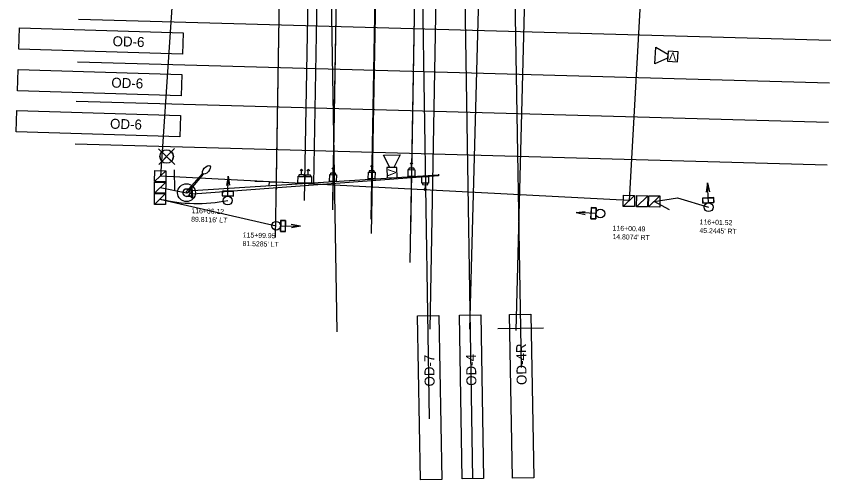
# Model space of a CAD drawing. Extents: x 925524 to 926006, y 853415 to 857998.
# Drawn here: x 925687.1 to 925916, y 853415.1 to 853545.3 of the extents above; entities that cross this region are included whole.
import ezdxf

# ---------------------------------------------------------------- set-up
doc = ezdxf.new("R2010")
doc.units = 0
for name, color, linetype in [('ConduitDB', 7, 'Continuous'), ('ConduitOT', 7, 'Continuous'), ('ConstLines', 7, 'Continuous'), ('Core', 7, 'Continuous'), ('DetectorVeh', 7, 'Continuous'), ('Luminaire', 7, 'Continuous'), ('NonPlottingEle_dp', 7, 'Continuous'), ('OverheadStr', 7, 'Continuous'), ('PedHead', 7, 'Continuous'), ('PoleFound', 7, 'Continuous'), ('PullBox', 7, 'Continuous'), ('ScratchEle2_dp', 7, 'Continuous'), ('ScratchEle_dp', 7, 'Continuous'), ('SignalHead', 7, 'Continuous'), ('SignPanel', 7, 'Continuous'), ('TextMinor', 7, 'Continuous')]:
    doc.layers.add(name, color=color, linetype=linetype)

msp = doc.modelspace()

# ---------------------------------------------------------------- linework, layer by layer
at = {"layer": 'ConduitDB'}
for p, q in [((925869.15, 853671.01), (925859.35, 853493.47)), ((925738.35, 853660.55), (925727.58, 853500.34)), ((925859.35, 853493.47), (925727.58, 853500.34)), ((925870.67, 853490.92), (925866.37, 853493.26))]:
    msp.add_line(p, q, dxfattribs=at)
msp.add_lwpolyline([(925866.37, 853493.26), (925872.9, 853494.28), (925881.63, 853491.63)], dxfattribs=at)
at = {"layer": 'ConduitOT'}
for p, q in [((925727.49, 853497.13), (925734.9, 853495.71)), ((925727.45, 853493.93), (925760.11, 853486.41))]:
    msp.add_line(p, q, dxfattribs=at)
msp.add_arc((925737.93, 853536.98), 44.31, 256.3165, 281.1337, dxfattribs=at)
at = {"layer": 'ConstLines'}
for p, q in [((925821.17, 853708.61), (925814.44, 853457.33)), ((925834.16, 853708.27), (925827.43, 853456.98)), ((925807.55, 853693.24), (925803.33, 853457.33)), ((925773.58, 853666.98), (925777.16, 853456.64))]:
    msp.add_line(p, q, dxfattribs=at)
at = {"layer": 'Core'}
for p, q in [((925727.08, 853508.03), (925731.66, 853503.6)), ((925727.15, 853503.62), (925731.54, 853508.16))]:
    msp.add_line(p, q, dxfattribs=at)
for points in [[(925727.95, 853507.19), (925729.32, 853505.86), (925728, 853504.5)], [(925730.64, 853507.23), (925729.32, 853505.86), (925730.69, 853504.54)]]:
    msp.add_lwpolyline(points, dxfattribs=at)
msp.add_circle((925729.32, 853505.86), 1.9, dxfattribs=at)
for start, end in [(135.9741, 225.9741), (315.9741, 45.9741)]:
    msp.add_arc((925729.32, 853505.86), 1.9, start, end, dxfattribs=at)
at = {"layer": 'DetectorVeh'}
for p, q in [((925870.19, 853534.66), (925870.12, 853533.49)), ((925793.21, 853502.77), (925792.04, 853502.75))]:
    msp.add_line(p, q, dxfattribs=at)
for points in [[(925870.12, 853533.49), (925866.5, 853531.95), (925866.78, 853536.63), (925870.19, 853534.66)], [(925792.04, 853502.75), (925790.23, 853506.24), (925794.91, 853506.32), (925793.21, 853502.77)]]:
    msp.add_lwpolyline(points, dxfattribs=at)
for points in [[(925870.07, 853532.67), (925872.87, 853532.5), (925873.04, 853535.31), (925870.24, 853535.48)], [(925791.22, 853502.74), (925791.27, 853499.93), (925794.08, 853499.98), (925794.03, 853502.79)]]:
    msp.add_lwpolyline(points, close=True, dxfattribs=at)
at = {"layer": 'Luminaire'}
for p, q in [((925739.42, 853501.09), (925734.75, 853495.85)), ((925739.61, 853500.93), (925735.06, 853495.58)), ((925735.06, 853495.58), (925734.75, 853495.85))]:
    msp.add_line(p, q, dxfattribs=at)
msp.add_ellipse((925740.48, 853502.12), major_axis=(0.98, 1.13), ratio=0.5, dxfattribs=at)
at = {"layer": 'NonPlottingEle_dp'}
for p, q in [((925763.22, 853675.01), (925759.78, 853483.16)), ((925779.22, 853674.95), (925775.92, 853490.92)), ((925790.22, 853674.76), (925786.81, 853484.28)), ((925801.22, 853674.56), (925797.82, 853484.67)), ((925704.58, 853544.44), (925915.95, 853538.55)), ((925704.24, 853532.45), (925915.62, 853526.55)), ((925703.94, 853521.45), (925915.31, 853515.56)), ((925703.6, 853509.46), (925914.98, 853503.56))]:
    msp.add_line(p, q, dxfattribs=at)
at = {"layer": 'OverheadStr'}
for p, q in [((925736.59, 853496.35), (925805.75, 853500.75)), ((925736.66, 853495.36), (925805.76, 853500.57)), ((925805.74, 853500.87), (925805.77, 853500.45)), ((925734.83, 853496.77), (925736.16, 853496.86)), ((925734.83, 853496.71), (925736.16, 853496.8)), ((925734.83, 853496.77), (925734.83, 853496.71)), ((925735.25, 853496.65), (925736.25, 853496.72)), ((925736.13, 853497.3), (925736.3, 853497.31)), ((925736.17, 853496.72), (925736.13, 853497.3)), ((925736.38, 853494.89), (925736.25, 853496.72)), ((925736.29, 853497.32), (925736.52, 853497.34)), ((925736.5, 853494.36), (925736.29, 853497.32)), ((925736.5, 853494.32), (925736.3, 853497.31)), ((925736.73, 853494.38), (925736.52, 853497.34)), ((925734.97, 853494.71), (925736.3, 853494.81)), ((925734.98, 853494.65), (925734.97, 853494.71)), ((925734.98, 853494.65), (925736.31, 853494.74)), ((925735.38, 853494.83), (925736.38, 853494.89)), ((925736.34, 853494.31), (925736.3, 853494.89)), ((925736.34, 853494.31), (925736.5, 853494.32)), ((925736.5, 853494.36), (925736.73, 853494.38))]:
    msp.add_line(p, q, dxfattribs=at)
msp.add_lwpolyline([(925735.92, 853495.51), (925735.88, 853496.05), (925735.58, 853496.49), (925735.1, 853496.73), (925734.57, 853496.69), (925734.12, 853496.39), (925733.89, 853495.91), (925733.92, 853495.37), (925734.22, 853494.93), (925734.7, 853494.69), (925735.24, 853494.73), (925735.68, 853495.03)], close=True, dxfattribs=at)
at = {"layer": 'PedHead'}
for p, q in [((925746.61, 853500.33), (925746.11, 853497.74)), ((925746.51, 853494.76), (925746.61, 853500.33)), ((925746.61, 853500.33), (925747.01, 853497.79)), ((925881.32, 853498.44), (925880.98, 853495.82)), ((925881.32, 853498.44), (925881.88, 853495.93)), ((925881.57, 853492.88), (925881.32, 853498.44)), ((925744.98, 853496.16), (925744.95, 853494.79)), ((925744.95, 853494.79), (925748.08, 853494.73)), ((925748.1, 853496.11), (925744.98, 853496.16)), ((925744.99, 853494.79), (925745.01, 853496.13)), ((925748.04, 853494.73), (925744.99, 853494.79)), ((925745.01, 853496.13), (925748.06, 853496.07)), ((925748.06, 853496.07), (925748.04, 853494.73)), ((925748.08, 853494.73), (925748.1, 853496.11)), ((925883.07, 853494.32), (925879.95, 853494.18)), ((925879.95, 853494.18), (925880.01, 853492.81)), ((925879.99, 853494.15), (925883.04, 853494.29)), ((925880.05, 853492.81), (925879.99, 853494.15)), ((925883.04, 853494.29), (925883.1, 853492.95)), ((925883.14, 853492.95), (925883.07, 853494.32)), ((925880.01, 853492.81), (925883.14, 853492.95)), ((925883.1, 853492.95), (925880.05, 853492.81)), ((925844.39, 853490.12), (925846.94, 853490.47)), ((925849.96, 853489.91), (925844.39, 853490.12)), ((925844.39, 853490.12), (925846.98, 853489.57)), ((925848.65, 853491.53), (925848.53, 853488.4)), ((925848.57, 853488.44), (925848.68, 853491.49)), ((925850.02, 853491.47), (925848.65, 853491.53)), ((925848.68, 853491.49), (925850.02, 853491.43)), ((925849.9, 853488.35), (925850.02, 853491.47)), ((925850.02, 853491.43), (925849.91, 853488.39)), ((925761.39, 853487.95), (925761.34, 853484.82)), ((925761.34, 853484.86), (925761.39, 853487.91)), ((925762.77, 853487.92), (925761.39, 853487.95)), ((925761.39, 853487.91), (925762.73, 853487.88)), ((925762.73, 853487.88), (925762.68, 853484.84)), ((925762.71, 853484.8), (925762.77, 853487.92)), ((925848.53, 853488.4), (925849.9, 853488.35)), ((925849.91, 853488.39), (925848.57, 853488.44)), ((925761.36, 853486.38), (925766.94, 853486.28)), ((925766.94, 853486.28), (925764.34, 853486.79)), ((925766.94, 853486.28), (925764.4, 853485.88)), ((925762.68, 853484.84), (925761.34, 853484.86)), ((925761.34, 853484.82), (925762.71, 853484.8))]:
    msp.add_line(p, q, dxfattribs=at)
for centre in [(925746.49, 853493.51), (925881.63, 853491.63), (925851.21, 853489.87), (925760.11, 853486.41)]:
    msp.add_circle(centre, 1.25, dxfattribs=at)
at = {"layer": 'PoleFound'}
msp.add_circle((925734.9, 853495.71), 2.5, dxfattribs=at)
at = {"layer": 'PullBox'}
for p, q in [((925725.94, 853498.81), (925725.98, 853501.94)), ((925725.94, 853498.81), (925729.1, 853501.89)), ((925725.98, 853501.94), (925729.1, 853501.89)), ((925729.1, 853501.89), (925729.06, 853498.77)), ((925725.91, 853495.59), (925725.95, 853498.71)), ((925725.91, 853495.59), (925729.08, 853498.67)), ((925729.06, 853498.77), (925725.94, 853498.81)), ((925725.95, 853498.71), (925729.08, 853498.67)), ((925729.08, 853498.67), (925729.03, 853495.55)), ((925725.87, 853492.39), (925725.91, 853495.52)), ((925725.87, 853492.39), (925729.04, 853495.47)), ((925729.03, 853495.55), (925725.91, 853495.59)), ((925725.91, 853495.52), (925729.04, 853495.47)), ((925729.04, 853495.47), (925728.99, 853492.35)), ((925857.67, 853491.85), (925857.73, 853494.97)), ((925857.67, 853491.85), (925860.85, 853494.92)), ((925857.73, 853494.97), (925860.85, 853494.92)), ((925860.85, 853494.92), (925860.8, 853491.79)), ((925861.39, 853491.78), (925861.44, 853494.91)), ((925861.39, 853491.78), (925864.57, 853494.85)), ((925861.44, 853494.91), (925864.57, 853494.85)), ((925864.57, 853494.85), (925864.51, 853491.73)), ((925864.78, 853491.72), (925864.83, 853494.85)), ((925864.78, 853491.72), (925867.96, 853494.79)), ((925864.83, 853494.85), (925867.96, 853494.79)), ((925867.96, 853494.79), (925867.9, 853491.67)), ((925728.99, 853492.35), (925725.87, 853492.39)), ((925860.8, 853491.79), (925857.67, 853491.85)), ((925864.51, 853491.73), (925861.39, 853491.78)), ((925867.9, 853491.67), (925864.78, 853491.72))]:
    msp.add_line(p, q, dxfattribs=at)
at = {"layer": 'ScratchEle2_dp'}
for p, q in [((925798.69, 853711.44), (925803.07, 853432.2)), ((925829.04, 853446.57), (925824.52, 853709.82)), ((925815.37, 853415.34), (925810.9, 853700.12)), ((925763.52, 853691.77), (925759.97, 853493.66)), ((925771.52, 853691.62), (925767.97, 853493.51)), ((925779.52, 853691.48), (925775.97, 853493.37)), ((925773.97, 853688.76), (925770.55, 853498.1)), ((925790.32, 853688.01), (925786.74, 853488.27)), ((925801.46, 853687.88), (925797.66, 853476.1)), ((925835.28, 853457.68), (925822.42, 853457.46))]:
    msp.add_line(p, q, dxfattribs=at)
at = {"layer": 'ScratchEle_dp'}
msp.add_line((925731.6, 853496.34), (925731.51, 853502.12), dxfattribs=at)
at = {"layer": 'SignalHead'}
for p, q in [((925786.58, 853503.09), (925786.99, 853503.48)), ((925786.96, 853501.87), (925786.99, 853503.48)), ((925787.38, 853503.07), (925786.99, 853503.48)), ((925797.76, 853503.8), (925798.17, 853504.19)), ((925798.14, 853502.58), (925798.17, 853504.19)), ((925798.56, 853503.78), (925798.17, 853504.19)), ((925766.82, 853501.9), (925767.23, 853502.3)), ((925767.2, 853500.69), (925767.23, 853502.3)), ((925767.62, 853501.89), (925767.23, 853502.3)), ((925768.73, 853501.87), (925769.13, 853502.26)), ((925769.1, 853500.65), (925769.13, 853502.26)), ((925769.52, 853501.86), (925769.13, 853502.26)), ((925776.72, 853501.17), (925775.49, 853501.19)), ((925775.73, 853502.39), (925776.14, 853502.79)), ((925776.11, 853501.18), (925776.14, 853502.79)), ((925776.53, 853502.38), (925776.14, 853502.79)), ((925787.57, 853501.86), (925786.35, 853501.88)), ((925798.75, 853502.57), (925797.52, 853502.59)), ((925767.81, 853500.68), (925766.58, 853500.7)), ((925769.72, 853500.64), (925768.49, 853500.66)), ((925801.35, 853497.98), (925802.58, 853497.96)), ((925801.54, 853496.77), (925801.93, 853496.36)), ((925801.96, 853497.97), (925801.93, 853496.36)), ((925802.34, 853496.75), (925801.93, 853496.36))]:
    msp.add_line(p, q, dxfattribs=at)
for points in [[(925786.02, 853501.49), (925787.89, 853501.46), (925787.86, 853499.58), (925785.98, 853499.62)], [(925797.19, 853502.2), (925799.07, 853502.17), (925799.03, 853500.29), (925797.16, 853500.33)], [(925766.25, 853500.31), (925768.13, 853500.28), (925768.09, 853498.4), (925766.22, 853498.44)], [(925768.16, 853500.28), (925770.04, 853500.24), (925770, 853498.37), (925768.13, 853498.4)], [(925775.16, 853500.8), (925777.04, 853500.77), (925777.01, 853498.89), (925775.13, 853498.93)], [(925802.91, 853498.35), (925801.03, 853498.38), (925801.07, 853500.26), (925802.94, 853500.22)]]:
    msp.add_lwpolyline(points, close=True, dxfattribs=at)
for points in [[(925786.34, 853501.49), (925787.57, 853501.46)], [(925797.52, 853502.2), (925798.74, 853502.17)], [(925766.58, 853500.3), (925767.8, 853500.28)], [(925768.48, 853500.27), (925769.71, 853500.25)], [(925775.49, 853500.79), (925776.72, 853500.77)], [(925802.58, 853498.35), (925801.36, 853498.38)]]:
    msp.add_lwpolyline(points, dxfattribs=at)
for centre, radius, start, end in [((925775.49, 853501.07), 0.121, 88.9741, 208.2939), ((925773.41, 853499.95), 2.25, 22.1907, 28.2939), ((925776.72, 853501.05), 0.121, 329.6543, 88.9741), ((925778.77, 853499.85), 2.25, 149.6543, 155.7575), ((925786.34, 853501.76), 0.121, 88.9741, 208.2939), ((925784.26, 853500.64), 2.25, 22.1907, 28.2939), ((925787.57, 853501.74), 0.121, 329.6543, 88.9741), ((925789.62, 853500.54), 2.25, 149.6543, 155.7575), ((925797.52, 853502.47), 0.121, 88.9741, 208.2939), ((925795.43, 853501.35), 2.25, 22.1907, 28.2939), ((925800.79, 853501.25), 2.25, 149.6543, 155.7575), ((925798.75, 853502.45), 0.121, 329.6543, 88.9741), ((925766.58, 853500.58), 0.121, 88.9741, 208.2939), ((925764.49, 853499.46), 2.25, 22.1907, 28.2939), ((925769.85, 853499.36), 2.25, 149.6543, 155.7575), ((925767.81, 853500.56), 0.121, 329.6543, 88.9741), ((925768.49, 853500.54), 0.121, 88.9741, 208.2939), ((925766.4, 853499.42), 2.25, 22.1907, 28.2939), ((925771.76, 853499.32), 2.25, 149.6543, 155.7575), ((925769.72, 853500.52), 0.121, 329.6543, 88.9741), ((925801.35, 853498.1), 0.121, 149.6543, 268.9741), ((925799.31, 853499.3), 2.25, 329.6543, 335.7575), ((925804.67, 853499.2), 2.25, 202.1907, 208.2939), ((925802.58, 853498.08), 0.121, 268.9741, 28.2939)]:
    msp.add_arc(centre, radius, start, end, dxfattribs=at)
at = {"layer": 'SignPanel'}
for q in [(925754.12, 853498.86), (925758.09, 853497.77), (925762.11, 853498.67)]:
    msp.add_line((925758.12, 853498.76), q, dxfattribs=at)
at = {"layer": 'TextMinor'}
for points in [[(925733.94, 853540.58), (925733.75, 853534.59), (925687.78, 853535.99), (925687.96, 853541.99), (925733.94, 853540.58)], [(925733.58, 853528.94), (925733.4, 853522.94), (925687.42, 853524.34), (925687.6, 853530.34), (925733.58, 853528.94)], [(925733.23, 853517.4), (925733.05, 853511.4), (925687.07, 853512.81), (925687.25, 853518.8), (925733.23, 853517.4)], [(925806.63, 853415.19), (925800.63, 853415.09), (925799.84, 853461.08), (925805.84, 853461.18), (925806.63, 853415.19)], [(925818.37, 853415.39), (925812.37, 853415.29), (925811.59, 853461.28), (925817.59, 853461.38), (925818.37, 853415.39)], [(925832.48, 853415.63), (925826.49, 853415.53), (925825.7, 853461.52), (925831.7, 853461.62), (925832.48, 853415.63)]]:
    msp.add_lwpolyline(points, dxfattribs=at)

# ---------------------------------------------------------------- texts
at = {"layer": 'DetectorVeh'}
for rotation, p in [(176.5443, (925872.62, 853535.05)), (90.9742, (925793.79, 853500.38))]:
    msp.add_text('V', height=2.25, rotation=rotation, dxfattribs=at).set_placement(p)
at = {"layer": 'NonPlottingEle_dp'}
for s, p in [('116+06.12', (925736.27, 853489.97)), ("89.8116' LT", (925736.2, 853487.57)), ('116+01.52', (925879.11, 853486.83)), ('116+00.49', (925854.66, 853485.07)), ("45.2445' RT", (925879.04, 853484.43)), ('115+99.95', (925750.7, 853483.16)), ("14.8074' RT", (925854.6, 853482.68)), ("81.5285' LT", (925750.64, 853480.76))]:
    msp.add_text(s, height=1.4, rotation=358.3939, dxfattribs=at).set_placement(p)
at = {"layer": 'TextMinor'}
for s, rotation, p in [('OD-6', 358.2527, (925714.1, 853536.89)), ('OD-6', 358.2527, (925713.75, 853525.24)), ('OD-6', 358.2527, (925713.39, 853513.7)), ('OD-4R', 90.9741, (925830.51, 853441.72)), ('OD-7', 90.9741, (925804.65, 853441.29)), ('OD-4', 90.9741, (925816.39, 853441.48))]:
    msp.add_text(s, height=2.8, rotation=rotation, dxfattribs=at).set_placement(p)

doc.saveas('drawing.dxf')
